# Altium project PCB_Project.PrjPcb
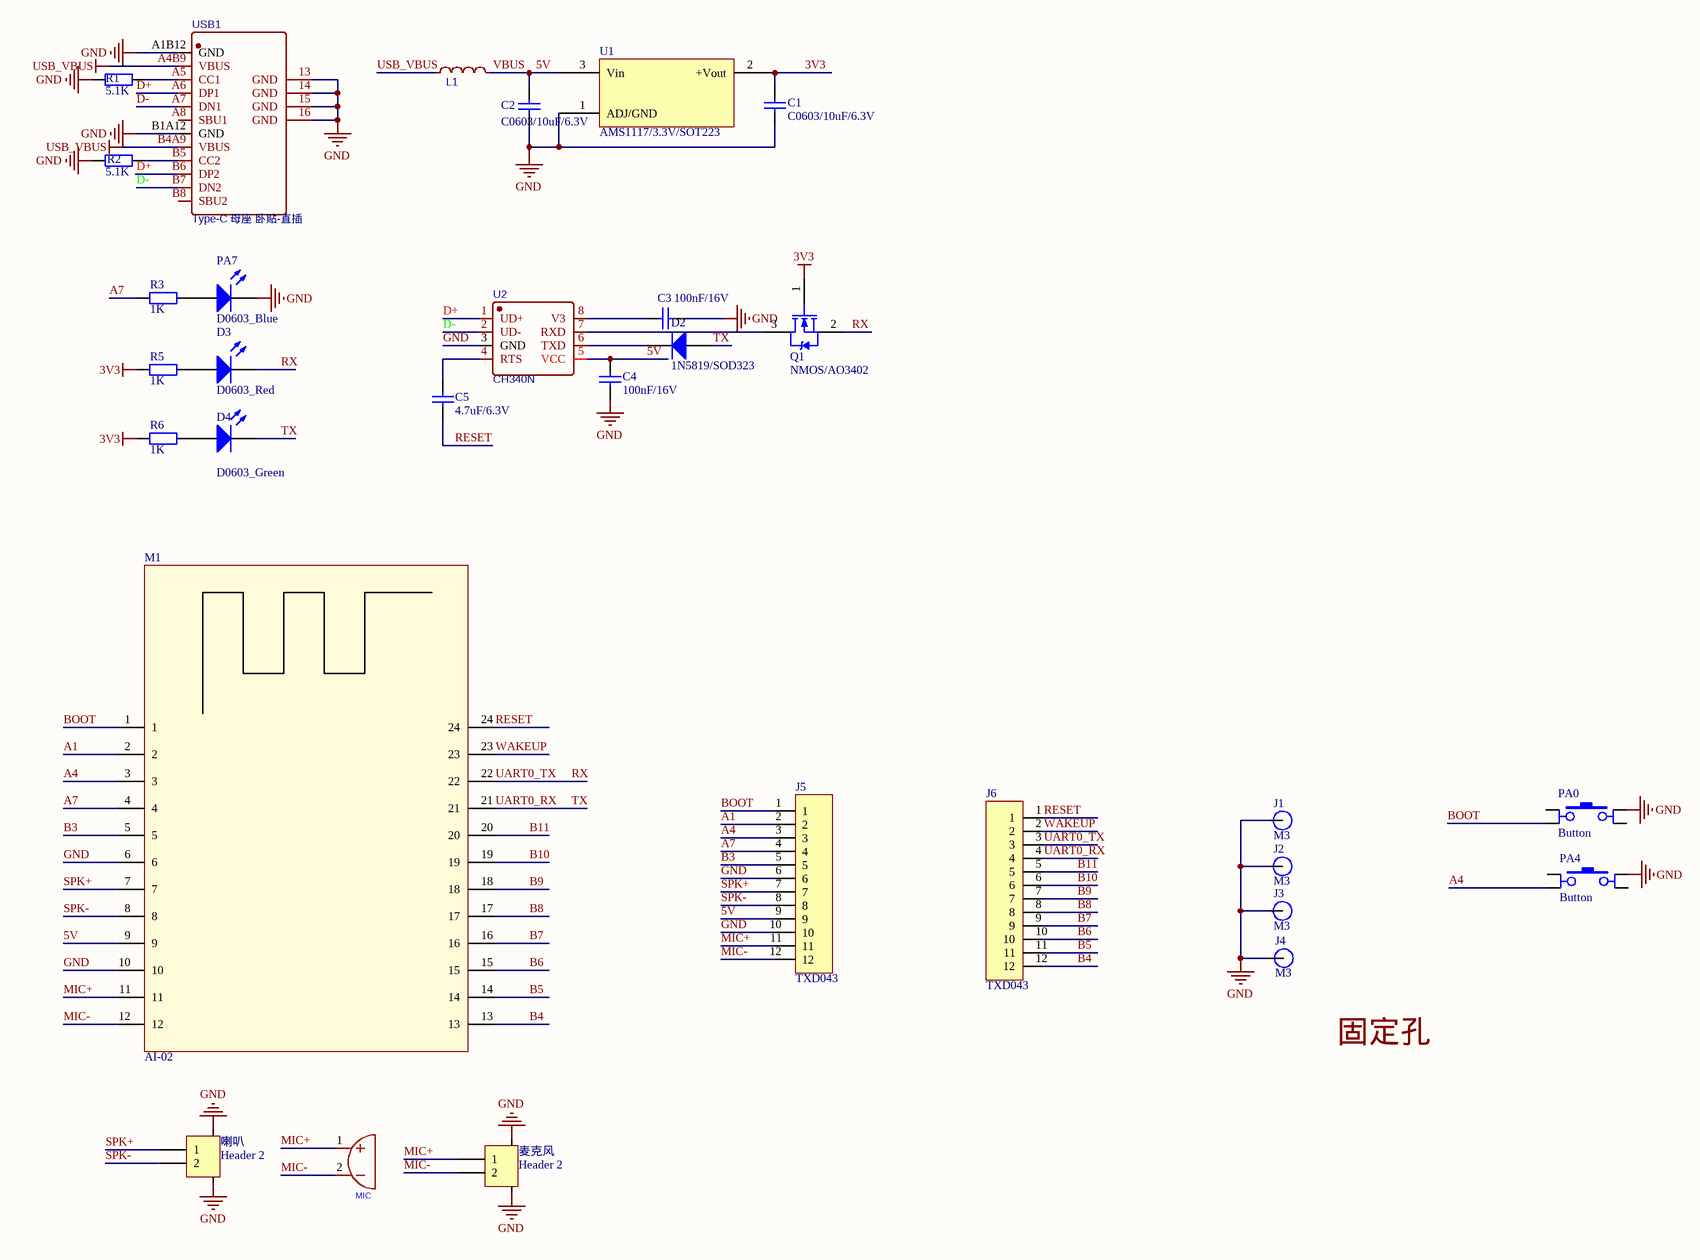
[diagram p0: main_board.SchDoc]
1 sheet, 31 parts. Net scope: global (net labels, ports and power ports of the same name join across sheets).
Board file: main_board.PcbDoc

## Sheet main_board.SchDoc
size OrCAD C

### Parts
C1  C0603/10uF/6.3V  [C0603]
C2  C0603/10uF/6.3V  [C0603]
C3  100nF/16V  [C0402]
C4  100nF/16V  [C0402]
C5  4.7uF/6.3V  [C0402]
D2  1N5819/SOD323  [SOD-323]
D3  D0603_Red  [D0603]
D4  D0603_Green  [D0603]
J1  M3  [M3 125X200]
J2  M3  [M3 125X200]
J3  M3  [M3 125X200]
J4  M3  [M3 125X200]
J5  TXD043  [PH_12PIN_DIP_2.54MM_180DEG]
J6  TXD043  [PH_12PIN_DIP_2.54MM_180DEG]
L1  L-0805  [L-0805]  (value not drawn)
M1  AI-02  [WM-AI-Module]
MIC  GMI6027P-2C30DB  [MIC-TH_BD6.0-P1.90-D0.4-L]  (value not drawn)
PA0  Button  [SW-SMD_4P-L4.2-W3.3-P2.15-LS5.1]
PA4  Button  [SW-SMD_4P-L4.2-W3.3-P2.15-LS5.1]
PA7  D0603_Blue  [D0603]
Q1  NMOS/AO3402  [SOT-23]
R1  5.1K  [R0402]
R2  5.1K  [R0402]
R3  1K  [R0402]
R5  1K  [R0402]
R6  1K  [R0402]
U1  AMS1117/3.3V/SOT223  [SOT223]
U2  CH340N  [SOP8]
USB1  Type-C 母座 卧贴-直插  [TYPE-C 母座 卧贴-直插]
喇叭  Header 2  [CONN-SMD_2P-P1.25-HC-1.25-2PWT]
麦克风  Header 2  [CONN-SMD_2P-P1.25-HC-1.25-2PWT]

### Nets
3V3: C1.2 Q1.1(G) R5.1 R6.1 U1.2(+Vout) U1.4
GND: C1.1 C2.1 C3.2 C4.1 J1.1(GND) J2.1(GND) J3.1(GND) J4.1(GND) J5.6 J5.10 M1.6 M1.10 PA0.1(PINA1) PA4.1(PINA1) PA7.2(K) R1.1 R2.1 U1.1(ADJ/GND) U2.3(GND) USB1.13(GND) USB1.14(GND) USB1.15(GND) USB1.16(GND) USB1.A1B12(GND) USB1.B1A12(GND) 喇叭.3 喇叭.4 麦克风.3 麦克风.4
USB_VBUS: L1.1 USB1.A4B9(VBUS) USB1.B4A9(VBUS)
5V: C2.2 C4.2 J5.9 L1.2 M1.9 U1.3(Vin) U2.5(VCC)  [also labelled VBUS]
A1: J5.2 M1.2
A4: J5.3 M1.3 PA4.3(PINB1)
A7: J5.4 M1.4 R3.1
B3: J5.5 M1.5
B4: J6.12 M1.13
B5: J6.11 M1.14
B6: J6.10 M1.15
B7: J6.9 M1.16
B8: J6.8 M1.17
B9: J6.7 M1.18
B10: J6.6 M1.19
B11: J6.5 M1.20
BOOT: J5.1 M1.1 PA0.3(PINB1)
D+: U2.1(UD+) USB1.A6(DP1) USB1.B6(DP2)
D-: U2.2(UD-) USB1.A7(DN1) USB1.B7(DN2)
MIC+: J5.11 M1.11 MIC.1 麦克风.1
MIC-: J5.12 M1.12 MIC.2 麦克风.2
RESET: C5.1 J6.1 M1.24
RX: D3.2(K) J6.3 M1.22 Q1.2(S)  [also labelled UART0_TX]
SPK+: J5.7 M1.7 喇叭.1
SPK-: J5.8 M1.8 喇叭.2
TX: D2.1(A) D4.2(K) J6.4 M1.21  [also labelled UART0_RX]
WAKEUP: J6.2 M1.23
NetC3_1: C3.1 U2.8(V3)
NetC5_2: C5.2 U2.4(RTS)
NetD2_2: D2.2(K) U2.6(TXD)
NetD3_1: D3.1(A) R5.2
NetD4_1: D4.1(A) R6.2
NetPA7_1: PA7.1(A) R3.2
NetQ1_3: Q1.3(D) U2.7(RXD)
NetR1_2: R1.2 USB1.A5(CC1)
NetR2_2: R2.2 USB1.B5(CC2)

Not connected (* = marked no-connect by the designer): PA0 2(PINA2) 4(PINB2); PA4 2(PINA2) 4(PINB2); USB1 A8(SBU1) B8(SBU2)

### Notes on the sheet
- 固定孔

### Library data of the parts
C1 C2 = C0603/10uF/6.3V: 01_物料名称: 电容; 02_规格参数: 贴片电容-0603-10UF±20%-6.3V-X5R; 04_物料编码: 10010012
C3 C4 = C0402/100nF/16V: 01_物料名称: 电容; 02_规格参数: 贴片电容-0402-100NF-±10%-16V-X7R; 04_物料编码: 10010002
C5 = C0402/4.7uF/6.3V: 01_物料名称: 电容; 02_规格参数: 贴片电容-0402-4.7UF±20%-6.3V-X5R; 04_物料编码: 10010006
D2 = 1N5819/SOD323: 01_物料名称: 二极管; 02_规格参数: 贴片肖特基二极管-1N5819-1A/40V-SOD323; 04_物料编码: 10060004
D3 = D0603_Red: 01_物料名称: 二极管; 02_规格参数: 贴片发光二极管-红色-0603; 04_物料编码: 10060002
D4 PA7 = D0603_Blue: 01_物料名称: 二极管; 02_规格参数: 贴片发光二极管-蓝色-0603; 04_物料编码: 10060003
J1-J4 = M3: 铜柱孔; 版权归属: 源创客
J5 J6 = TXD043: 4.3寸TFT 深圳市给力光电有限公司043202B0-40-N; BOM名称: 4.3寸TFT屏
L1 = L-0805: BOM_Manufacturer: Sunlord; BOM_Manufacturer Part: SZ1608G331TF; nameAlias: Value(H); Value: 330Ω
MIC = GMI6027P-2C30DB: Manufacturer: INGHAi(赢海); Add into BOM: yes
PA0 PA4 = BUTTON: Part Number: BUTTON_6x6_STAND; 02_规格参数: 按键开关-6x6-立式-直插
Q1 = AO3402/SOT-23: 01_物料名称: 场效应管; 02_规格参数: MOS管，场效应管 规格：AO3402 SOT-23 N沟道,-30V,-4  A,55mΩ@-10V
R1 R2 = R0402/5.1K: 01_物料名称: 贴片电阻; 02_规格参数: 贴片电阻-0402-5.1K±5%-1/16W; 04_物料编码: 10020006
R3 R5 R6 = R0402/1K: 01_物料名称: 贴片电阻; 02_规格参数: 贴片电阻-0402-1K±5%-1/16W; 04_物料编码: NC
U1 = AMS1117/3.3V/SOT223: 01_物料名称: 芯片; 02_规格参数: 电源芯片-LDO-AMS1117-3.3V-1A/15V-SOT223; 04_物料编码: 10050004
U2 = CH330N/SOP8: 01_物料名称: 芯片; 02_规格参数: USB转串口芯片-CH330N-SOP8; 04_物料编码: 10050005; Value: CH330N
USB1 = Type-C 母座 卧贴-直插: BOM_Manufacturer: XUNPU; BOM_Manufacturer Part: TYPEC-304-BCP16; Contributor: LCSC
喇叭 麦克风 = Header 2: Header, 2-Pin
